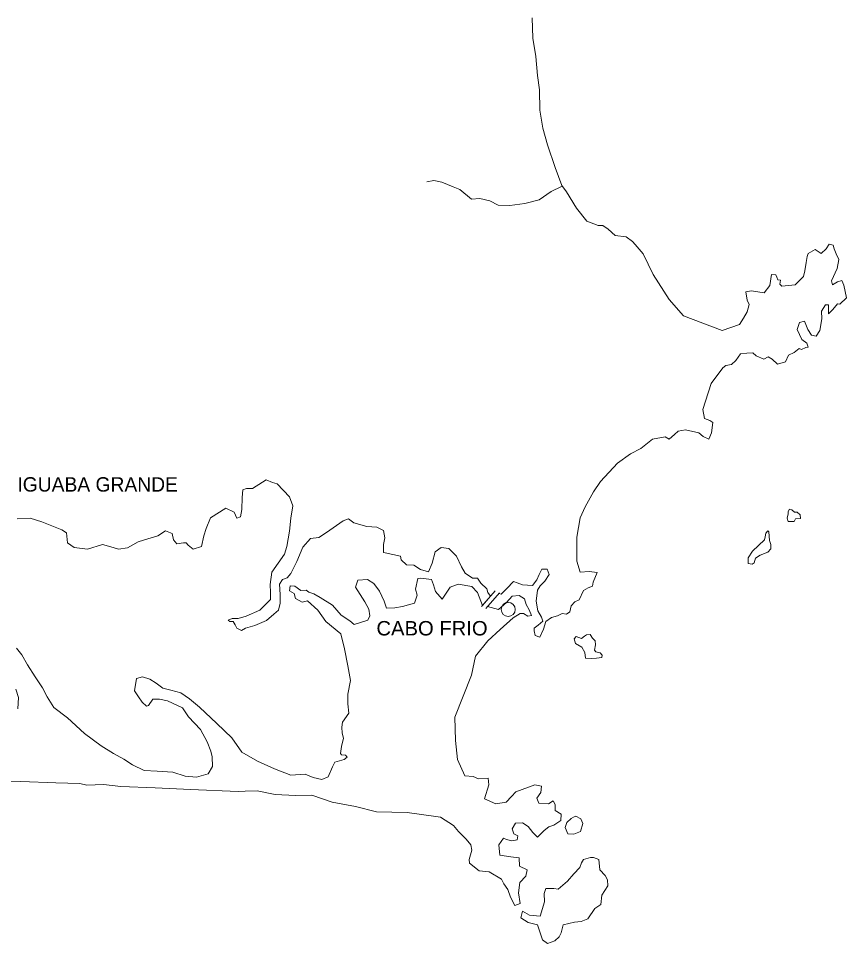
# Model space of a CAD drawing. Extents: x 47169 to 972804, y 7447977 to 9608469.
# Drawn here: x 169220 to 205477, y 7452014 to 7492492 of the extents above; entities that cross this region are included whole.
import ezdxf

# ---------------------------------------------------------------- set-up
doc = ezdxf.new("R2010")
doc.units = 0
doc.header["$LTSCALE"] = 270
doc.layers.add('1', color=7, linetype='Continuous', lineweight=13)
doc.layers.add('2', color=7, linetype='Continuous', lineweight=13)
doc.layers.add('3', color=7, linetype='Continuous')

msp = doc.modelspace()

# ---------------------------------------------------------------- linework, layer by layer
at = {"layer": '1'}
for p, q in [((190085.2, 7467440.9), (189495.8, 7466758.9)), ((190289, 7467357.6), (189686.5, 7466680.1)), ((189891.2, 7467216.4), (189540, 7466810.1)), ((189891.2, 7467216.4), (189540, 7466810.1))]:
    msp.add_line(p, q, dxfattribs=at)
for points in [[(204879.8, 7479764.3), (205080.5, 7480012.1), (205183.7, 7479991.9), (205476.6, 7480263.6), (205362.9, 7480826.7), (205266.5, 7481024.3), (205082.6, 7480965.3), (204869.2, 7480839.2), (204824.6, 7481015.7), (205071.2, 7481552.5), (205145.9, 7481941.9), (205017.6, 7482194.4), (204931.1, 7482414.4), (204897.1, 7482580), (204721.7, 7482609.8), (204581.7, 7482407.6), (204369.8, 7482203.9), (204098.9, 7482387.1), (203804.1, 7482215.1), (203755.3, 7482081.2), (203709.1, 7481814.2), (203654.5, 7481447.4), (203587.4, 7481202.2), (203234.6, 7480840.7), (202639.4, 7480784.7), (202555.7, 7480860.7), (202593.3, 7481038.7), (202469.6, 7481058.5), (202426.3, 7481168.5), (202383.2, 7481267.4), (202187.6, 7481285.7), (202125, 7480807.9), (201874.1, 7480492.6), (201317.3, 7480581.4), (201071.5, 7480532.3), (201130.1, 7480167.6), (201216, 7479980.9), (201129.8, 7479657.8), (200970.9, 7479377.5), (200791.1, 7479108), (200025.5, 7478837.9), (198337.2, 7479480.6), (197716.4, 7480199.9), (197006, 7481283.1), (196566.3, 7482194.4), (196229.2, 7482597.8), (196103, 7482739.4), (195831.8, 7482933.5), (195347.2, 7483001.4), (195043.6, 7483272.4), (194803.8, 7483433.9), (194608.5, 7483429.9), (194100.9, 7483619.3), (193657.5, 7484186.8), (193211.1, 7484909.4), (193010.2, 7485182.5), (192726.8, 7485974.9), (192388, 7486965.7), (192177.9, 7487693), (192048.9, 7488477.5), (192030.8, 7489375), (191946.2, 7489994), (191867.6, 7490834.9), (191738.3, 7491630.4), (191710.1, 7492516.6)], [(193000.8, 7485137.9), (192542.4, 7484918.1), (192015.1, 7484552.7), (191390.9, 7484395.9), (190734.6, 7484305), (190230.2, 7484328), (189856.3, 7484508.9), (189422.3, 7484610.9), (189052.7, 7484581.2), (188550.4, 7485003.2), (188249.8, 7485119), (187751.8, 7485330.5), (187410.9, 7485401.1), (187103.6, 7485339.4)], [(190258.8, 7467323.7), (190362, 7467303.7), (190603.6, 7467541.4), (190895.1, 7467857.8), (191060.7, 7467794.6), (191288.4, 7467710.6), (191720.4, 7467686.2), (191910.5, 7467933.9), (192019, 7468157.8), (192137.4, 7468393), (192363.4, 7468397.6), (192450.5, 7468155.5), (192261, 7467874.5), (192059.9, 7467659.8), (191940.3, 7467480), (191888.6, 7466991.2), (191958.8, 7466571.4), (192118.5, 7466297.5), (192173.5, 7466121.3), (191971.7, 7465939.8), (191799.7, 7465814.4), (191802.2, 7465692.5), (191847.3, 7465493.9), (192054.2, 7465420.5), (192211.5, 7465767.3), (192307.4, 7466101.9), (192560.4, 7466284.4), (192826, 7466356.3), (193029.6, 7466449.1), (193215.1, 7466419.6), (193356.8, 7466522.3), (193423.3, 7466789.7), (193584.2, 7466959.2), (193767.2, 7467051.6), (193954.2, 7467454.4), (194167.4, 7467580.7), (194361.1, 7467651.1), (194388.3, 7467829), (194564.9, 7468242.7), (194204.4, 7468290.9), (193814.6, 7468260.8), (193661, 7468745.5), (193670.5, 7469798.7), (193807.5, 7470644), (194034, 7471125.2), (194390.8, 7471775.3), (194700, 7472236.1), (195444.5, 7473027), (196011.7, 7473437.4), (196469.3, 7473679.4), (196985.4, 7474077.7), (197538.1, 7474188.5), (197714.9, 7474081.2), (197947.2, 7474285.3), (198108.7, 7474432.6), (198426.1, 7474494.4), (199014.4, 7474362), (199202.6, 7474199.5), (199441.3, 7474082.2), (199559.1, 7474361.7), (199622, 7474817.4), (199486.7, 7474903.4), (199259, 7474987.6), (199179.1, 7475385), (199295.4, 7475742), (199557.4, 7476523.1), (200068.2, 7477198.3), (200189.5, 7477300.5), (200435.2, 7477349.6), (200627.1, 7477519.7), (200837, 7477823.1), (201114, 7477850.7), (201370.6, 7477866.9), (201517.1, 7477736.7), (201859.4, 7477577.2), (202052.4, 7477691.8), (202219, 7477584.3), (202449.4, 7477367.1), (202807, 7477473.9), (202935, 7477764.5), (203179.4, 7477880.2), (203402.1, 7478050.8), (203505.8, 7478008.5), (203699.2, 7478100.9), (203791.5, 7478113.8), (203736.9, 7478279), (203517.9, 7478441), (203314, 7478880.4), (203410.9, 7479181.5), (203635.9, 7479241.3), (203786.9, 7478878.5), (203945.7, 7478637.8), (204152.3, 7478586.4), (204312, 7478833.3), (204394.5, 7479344.8), (204387.8, 7479688.3), (204557.1, 7479968.7), (204690.9, 7479960.2), (204694.8, 7479760.7), (204688.4, 7479561.1), (204879.8, 7479764.3)], [(169157, 7470601.9), (169732, 7470625.5), (170239, 7470470.3), (171120.3, 7470112.5), (171318.3, 7469983.7), (171369, 7469541.3), (171661.2, 7469337), (172238.1, 7469271.9), (172901.6, 7469474.8), (173263.5, 7469371.7), (173604.8, 7469268.2), (173993.9, 7469332), (174461.1, 7469586), (174889.9, 7469717.2), (175318.4, 7469859.4), (175663.1, 7470077.5), (175943, 7469961.5), (176010.8, 7469674.7), (176158.4, 7469500.5), (176445.1, 7469551), (176558, 7469553.4), (176642.6, 7469444.3), (176862.1, 7469271.6), (177239.9, 7469379.5), (177343, 7469847.3), (177438.8, 7470170.9), (177624.1, 7470640.5), (178293.3, 7471064.9), (178667.1, 7470884.4), (178785.4, 7470631.9), (178938.6, 7470679.5), (178993.4, 7471002.2), (179013.2, 7471523.7), (179036.7, 7471867.8), (179210.1, 7471926.9), (179467.2, 7471921.3), (179903.3, 7472196.6), (180065.5, 7472299.8), (180345.4, 7472183.8), (180541.8, 7472132.5)], [(180541.8, 7472132.5), (181088.3, 7471556.4), (181230, 7471171.4), (181138.7, 7470626.2), (181089, 7470059.8), (180969.5, 7469392.1), (180873.8, 7469057.5), (180315.3, 7468258.5), (180244.4, 7467724.9), (180251.9, 7467370.3), (180248, 7467070.9), (179785.2, 7466606.5), (179195.1, 7466339), (178837.6, 7466242.7), (178570.6, 7466237), (178407.7, 7466167.1), (178470.8, 7466101.9), (178624.8, 7466105.2), (178710, 7465962.8), (178785.2, 7465809.2), (178982.4, 7465713.6), (179165.1, 7465817.3), (179563.4, 7465925.5), (180072.4, 7466147), (180395.1, 7466431), (180607.2, 7466601.7), (180683, 7466902.7), (180674.8, 7467290.5), (180644.7, 7467744.4), (180774, 7467946.7), (180988.2, 7468017.8), (181138.5, 7468198.3), (181414.9, 7468736.3), (181669.1, 7469351.4), (182000.1, 7469735.3), (182368.9, 7469787.4), (182713.9, 7469994.2), (183442.9, 7470508.3), (183677.5, 7470590.8), (183907, 7470429.3), (184475.6, 7470263.8), (184918.1, 7470228.7), (185208.9, 7470079.5), (185256.5, 7469770.1), (185201.1, 7469469.7), (185208.2, 7469126.1), (185270.1, 7469116.3), (185941, 7468964), (185975.3, 7468798.4), (186205.8, 7468581.5), (186524.6, 7468565.9), (186816.1, 7468383.5), (187177.8, 7468280.2), (187334.3, 7468660.3), (187468, 7469150.8), (187731.1, 7469344.7), (188060.9, 7469296.1), (188396.6, 7468959.4), (188621.8, 7468498.4), (188781.6, 7468224.6), (189094.4, 7467998.2), (189320.3, 7468002.9), (189468.7, 7467784.2), (189730.6, 7467534.6), (189775.1, 7467369.2), (189891.2, 7467216.4)], [(189540, 7466810.1), (189312.8, 7467370.8), (189070.9, 7467643), (188473.1, 7467741.5), (188126.7, 7467601.4), (187777.8, 7467084.2), (187483.2, 7467421.8), (187395.1, 7467708.2), (187297.9, 7467939), (186834.4, 7467995.9), (186700.9, 7467993.1), (186608.1, 7467514.5), (186675, 7467260.9), (186559.1, 7466903.8), (186038.2, 7466759.9), (185700.5, 7466697.5), (185330.8, 7466689.8), (185232, 7466998.1), (185027.9, 7467426.2), (184784.5, 7467764.8), (184503.3, 7467947.4), (184082.8, 7467916.5), (183976.3, 7467603.8), (184390.4, 7466958.4), (184561.4, 7466640.5), (184608.5, 7466353.2), (184520, 7466162.9), (183918, 7465973), (183729.6, 7466135.3), (183354.7, 7466382.4), (182965.4, 7466817.7), (182424.3, 7467150), (182153.6, 7467321.7), (181926.2, 7467383.4), (181821.4, 7467481), (181585.5, 7467465), (181324.8, 7467647.9), (181119, 7467665.8), (181092.8, 7467443.5), (181290.5, 7467325.7), (181356.8, 7467105.4), (181647.6, 7466956.3), (181872.6, 7467005.4), (182322.7, 7466604.7), (182682.6, 7466102.2), (183341.1, 7465561.8), (183488.2, 7464910.8), (183647.5, 7464171.3), (183763.9, 7463519.7), (183642.8, 7462929.6), (183641.6, 7462497.2), (183691.2, 7462088), (183411.7, 7461705.2), (183385.6, 7461483), (183391.1, 7461217), (183447.1, 7460996.5), (183362.2, 7460639.9), (183317.4, 7460328.6), (183370.1, 7460263.2), (183544.8, 7460255.8), (183618.6, 7460168.6), (183477, 7460065.9), (183079, 7459946.6), (182970.3, 7459744.8), (182774.1, 7459308.3), (182509.6, 7459191.9), (182117.5, 7459283.4), (181765.5, 7459420), (181150.2, 7459384.9), (180425.6, 7459657.8), (179689.4, 7459996.9), (178992.9, 7460392.3), (178568.9, 7461015.2), (177898.2, 7461643.9), (177143.4, 7462359.5), (176704.4, 7462715.9), (176328.9, 7462985), (175895.1, 7463097.7), (175543.9, 7463189.9), (175251.6, 7463405.4), (174970.6, 7463576.7), (174650, 7463680.7), (174384.5, 7463608.4), (174293.3, 7463074.3), (174473.6, 7462812.1), (174632.8, 7462571.6), (174821.4, 7462398.3), (174913.1, 7462433.5), (175102.4, 7462703.7), (175400.1, 7462710.1), (175740.6, 7462639.8), (176404.8, 7462321.5), (176659.7, 7461927.8), (177195.3, 7461373.9), (177484.1, 7460836.8), (177646.9, 7460430), (177703.4, 7460187.4), (177712.4, 7459766.2), (177524.3, 7459440.7), (177013.9, 7459296.7), (176520.3, 7459330.5)], [(187698.2, 7457537.7), (188270.2, 7457183.7), (188491.4, 7456911.2), (188826.9, 7456574.5), (189026.9, 7456334.7), (189072.8, 7456102.9), (188958.1, 7455690.3), (188961.5, 7455524.1), (189389.3, 7455189.3), (189831.4, 7455154.1), (190371.8, 7454832.6), (190468.4, 7454624), (190648.1, 7454372.7), (190757.5, 7454042.4), (190960.2, 7453669.7), (191184.1, 7453763), (191113, 7454227.1), (191165.2, 7454682.7), (191436.5, 7454965.4), (191492.4, 7455243.7), (191150.6, 7455391.9), (191142.9, 7455768.6), (190782.8, 7455805.5), (190298.8, 7455884.3), (190258.6, 7456338), (190458.1, 7456619.2), (190592.7, 7456566.5), (190819.8, 7456504.7), (191054.9, 7456553.9), (191082, 7456731.8), (190916.2, 7456806), (190839.6, 7457037.2), (190988.5, 7457284.2), (191296.4, 7457290.5), (191535.6, 7457140.2), (191746.5, 7456867.4), (191945.7, 7456660.8), (192237.2, 7456966.1), (192439.5, 7457114.4), (192663.8, 7457185.5), (192967.6, 7457391.2), (192982.5, 7457668.6), (192722.3, 7457840.7), (192717.1, 7458095.5), (192631.6, 7458260.1), (192429.1, 7458122.9), (192007.5, 7458158.6), (191910.8, 7458367.3), (192090.3, 7458625.9), (192125.9, 7458892.7), (191826.7, 7458964.2), (191001.6, 7458648), (190800.5, 7458444.3), (190569.4, 7458195.6), (190119.3, 7458119.9), (189632.2, 7458342.6), (189814.6, 7458956.1), (189787.9, 7459254.9), (189357.3, 7459223.8), (189129.5, 7459318.9), (188759.4, 7459344.5), (188436.3, 7460069.5), (188357.6, 7460899.3), (188326.2, 7461918.5), (189058.6, 7463751.7), (189236.5, 7464586.8), (189767.2, 7465251.7), (190311.4, 7465761.8), (190876.1, 7466272.2), (191190.8, 7466456), (191334.6, 7466458.9), (191521.9, 7466340.8), (191685.7, 7466366.3), (191577.8, 7466619.1), (191449.8, 7466849.2), (191373, 7467091.6), (191143.9, 7467242.1), (190836.3, 7467213.6), (190585.1, 7466942.4), (190231.8, 7466635.9), (189756.8, 7466759.2)], [(176520.3, 7459330.5), (175982.5, 7459507.4), (175293.7, 7459548), (174717.7, 7459591), (174209.2, 7459835), (173834.2, 7460081.9), (173377, 7460327), (172835.8, 7460659), (172115.5, 7461197.7), (171360.9, 7461890.9), (170765.6, 7462343.5), (170478.2, 7462802.9), (170274.4, 7463197.6), (169945.2, 7463689.4), (169615.5, 7464203.3), (169369.6, 7464641.4), (169126.9, 7464935.5)], [(169104.7, 7463138.8), (169225.6, 7462775.5), (169185.2, 7462275.7)], [(168515.1, 7459123.1), (169316.4, 7459107.5), (170858.2, 7459041.5), (171906.4, 7459008.9), (172205.7, 7458937.8), (172944.5, 7458965), (173706.1, 7458881.7), (175206.6, 7458825.5), (176748.5, 7458747.8), (178845, 7458659.6), (179142.4, 7458677), (179665.6, 7458699.2), (180459.6, 7458538.7), (181353.9, 7458491.2), (182062, 7458506.1), (182961.7, 7458203.6), (183972.1, 7458003.1), (184900.8, 7457778.7), (186246.2, 7457751.4), (186771.5, 7457673.7), (187698.2, 7457537.7)]]:
    msp.add_lwpolyline(points, dxfattribs=at)
for points in [[(203190.8, 7470476.2), (202923.6, 7470482.1), (202879.6, 7470625.3), (202917, 7470814.5), (202914.9, 7470925.2), (202974.5, 7471026.2), (203078.1, 7470983.9), (203193, 7470886.4), (203316.2, 7470888.8), (203441.9, 7470769.3), (203455.2, 7470614.4), (203250, 7470599.3)], [(201947.3, 7469975.2), (202027.5, 7470076.5), (202079.7, 7470033.2), (202107.9, 7469645.8), (202162.7, 7469469.5), (202166.4, 7469281.2), (202035.6, 7469145.6), (201699.3, 7469005.9), (201496.4, 7468880), (201438.9, 7468668.3), (201347.6, 7468611), (201172.4, 7468640.8), (201167.6, 7468884.6), (201356.7, 7469187.6), (201629.2, 7469436.8), (201881.3, 7469674.6), (201919.8, 7469808.3)], [(194004.9, 7465460.2), (194085.7, 7465528.3), (194249.9, 7465531.6), (194355.7, 7465378.6), (194471.1, 7465259), (194485, 7465081.9), (194448.6, 7464848.4), (194501.3, 7464782.9), (194687.2, 7464731.3), (194771.4, 7464633.2), (194763.3, 7464522.2), (194527.5, 7464506.3), (194301.8, 7464490.7), (194044.9, 7464496.6), (194019.2, 7464751), (193881.1, 7464981), (193610.8, 7465141.8), (193545.1, 7465340), (193645.5, 7465452.9), (193873.4, 7465357.7)], [(193519, 7457535.5), (193620.7, 7457581.9), (193848.9, 7457464.6), (193924.8, 7457266.6), (193829.2, 7456921), (193533.9, 7456804.1), (193266.9, 7456809.8), (193158.6, 7457084.7), (193225.9, 7457307.8), (193417.3, 7457489)], [(193877.7, 7455547.4), (193967.1, 7455693.3), (194263.1, 7455777), (194396.4, 7455779.7), (194634.4, 7455684.7), (194674.5, 7455231), (194905.1, 7454991.9), (195011.8, 7454794.5), (195027.2, 7454539.9), (194768.5, 7454135.5), (194715.3, 7453724.3), (194452.2, 7453541.6), (194143.2, 7453091.9), (193858.2, 7452975.2), (193561.2, 7452947), (193071.1, 7452826.1), (192985.8, 7452480.7), (192897.1, 7452301.6), (192705.6, 7452131.4), (192389.9, 7452014), (192160.8, 7452175.6), (191952.3, 7452836.5), (191539.7, 7452938.9), (191217.3, 7453142.9), (191293.5, 7453432.7), (191594.9, 7453250.4), (192067.6, 7453215.8), (192249.8, 7453840.3), (192242.4, 7454205.9), (192309.9, 7454417.9), (192658.9, 7454414), (192844.2, 7454384.5), (193257.6, 7454747.7), (193538.6, 7455063.8), (193799.9, 7455335.2)]]:
    msp.add_lwpolyline(points, close=True, dxfattribs=at)
at = {"layer": '2'}
msp.add_ellipse((190663.3, 7466633.6), major_axis=(0, 308.1), ratio=0.999989, dxfattribs=at)

# ---------------------------------------------------------------- texts
at = {"layer": '3'}
msp.add_text('IGUABA GRANDE', height=630.7, dxfattribs=at).set_placement((169172.2, 7471788.6))
at = {"layer": '3', "width": 1.05}
msp.add_text('CABO FRIO', height=630.3, dxfattribs=at).set_placement((184893.5, 7465494.5))

doc.saveas('drawing.dxf')
